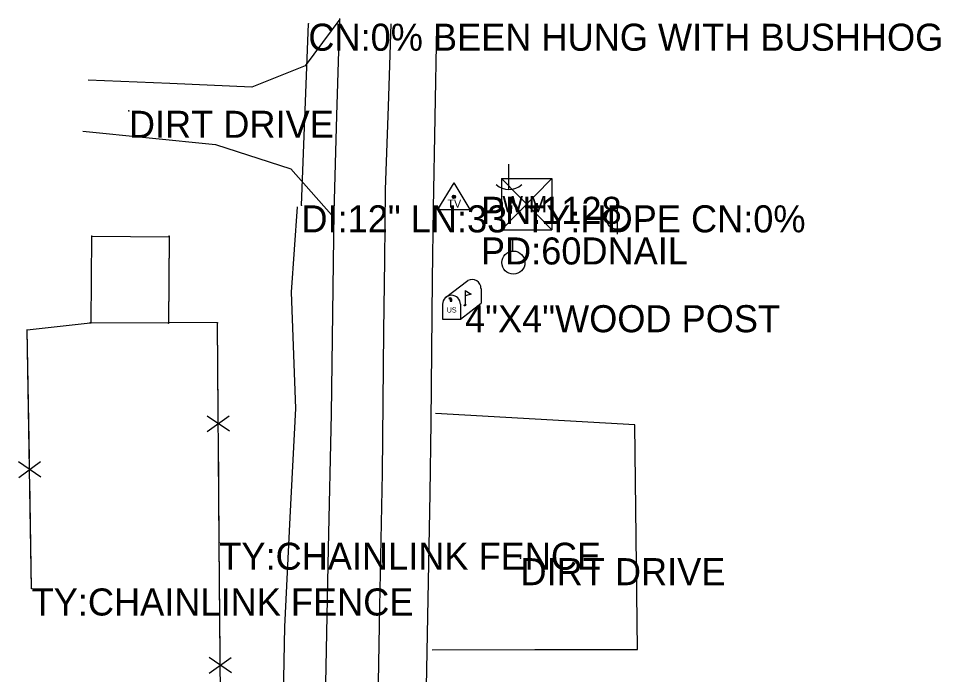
# Model space of a CAD drawing. Extents: x 1050807 to 1053552, y 395828 to 398415.
# Drawn here: x 1051868.7 to 1052039.2, y 398241.2 to 398362.4 of the extents above; entities that cross this region are included whole.
import ezdxf

# ---------------------------------------------------------------- set-up
doc = ezdxf.new("R2010")
doc.units = 0
for name, color, linetype in [('S_BUILDING', 7, 'Continuous'), ('S_CROSS_DRAIN', 7, 'Continuous'), ('S_CROSS_DRAIN_ANNOT', 7, 'Continuous'), ('S_DRG_PT_SYM', 7, 'Continuous'), ('S_DRIVEWAY', 7, 'Continuous'), ('S_EDGE_PAVEMENT', 7, 'Continuous'), ('S_FENCE', 7, 'Continuous'), ('S_FENCE_ANNOT', 7, 'Continuous'), ('S_GRAVEL_ROAD', 7, 'Continuous'), ('S_MAILBOX', 7, 'Continuous'), ('S_MAILBOX_ANNOT', 7, 'Continuous'), ('S_MSC_PT_SYM', 7, 'Continuous'), ('S_PAVEMENT_CROWN', 7, 'Continuous'), ('S_SECONDARY_CTL', 7, 'Continuous'), ('S_SECONDARY_CTL_ANNOT', 7, 'Continuous'), ('S_STR_PT_SYM', 7, 'Continuous'), ('S_SURVEY_TEXT_ANNOT', 7, 'Continuous'), ('S_UTILITY_POLE', 7, 'Continuous'), ('S_WATER_UTILITIES', 7, 'Continuous')]:
    doc.layers.add(name, color=color, linetype=linetype)

msp = doc.modelspace()

# ---------------------------------------------------------------- linework, layer by layer
at = {"layer": 'S_BUILDING'}
for p, q in [((1051882.09, 398306.19), (1051882.22, 398322.19)), ((1051882.22, 398322.19), (1051896.52, 398322.08)), ((1051896.52, 398322.19), (1051896.39, 398306.08)), ((1051896.52, 398322.08), (1051896.39, 398306.08)), ((1051896.39, 398306.08), (1051882.09, 398306.19))]:
    msp.add_line(p, q, dxfattribs=at)
at = {"layer": 'S_CROSS_DRAIN'}
msp.add_line((1051920.99, 398327.88), (1051922.27, 398361.44), dxfattribs=at)
at = {"layer": 'S_DRG_PT_SYM'}
for points in [[(1051922.27, 398361.44), (1051922.27, 398361.49), (1051922.27, 398361.44), (1051922.22, 398361.44), (1051922.27, 398361.44), (1051922.27, 398361.39), (1051922.27, 398361.44), (1051922.32, 398361.44)], [(1051920.99, 398327.88), (1051920.99, 398327.93), (1051920.99, 398327.88), (1051920.94, 398327.88), (1051920.99, 398327.88), (1051920.99, 398327.83), (1051920.99, 398327.88), (1051921.04, 398327.88)]]:
    msp.add_lwpolyline(points, dxfattribs=at)
at = {"layer": 'S_DRIVEWAY'}
for points in [[(1051928.11, 398362.27), (1051921.67, 398353.63), (1051911.81, 398349.74), (1051896.68, 398350.36), (1051881.55, 398350.99)], [(1051880.57, 398341.55), (1051905.13, 398339.1), (1051919.01, 398334.63), (1051926.56, 398326.11)], [(1051945.15, 398245.76), (1051964.14, 398245.8), (1051983.12, 398245.84), (1051982.87, 398266.58), (1051982.61, 398287.32), (1051964.2, 398288.35), (1051945.79, 398289.39)]]:
    msp.add_lwpolyline(points, dxfattribs=at)
at = {"layer": 'S_EDGE_PAVEMENT'}
for points in [[(1051925.48, 398239.54), (1051926, 398264.45), (1051926.52, 398289.36), (1051926.77, 398307.98), (1051927.03, 398326.6), (1051927.55, 398344.5), (1051928.06, 398362.41)], [(1051934.63, 398023.1), (1051930.06, 398027.26), (1051929.8, 398038.82), (1051925.96, 398053.99), (1051931.83, 398077.54), (1051938.69, 398100.99), (1051941.54, 398122.27), (1051942, 398134.91), (1051942.46, 398147.55), (1051942.93, 398160.19), (1051943.39, 398172.83), (1051943.59, 398197.73), (1051943.79, 398222.64), (1051944.04, 398235.63), (1051944.3, 398248.63), (1051944.55, 398261.62), (1051944.81, 398274.62), (1051944.95, 398287.8), (1051945.09, 398300.98), (1051945.24, 398314.17), (1051945.38, 398327.35), (1051945.7, 398344.1), (1051946.02, 398360.85)]]:
    msp.add_lwpolyline(points, dxfattribs=at)
at = {"layer": 'S_FENCE'}
for p, q in [((1051870.31, 398304.86), (1051881.92, 398306.16)), ((1051905.46, 398306.18), (1051896.47, 398306.24)), ((1051905.81, 398265.54), (1051905.46, 398306.18)), ((1051871.11, 398257.09), (1051870.31, 398304.86)), ((1051907.68, 398286.12), (1051903.56, 398288.95)), ((1051907.68, 398286.12), (1051903.56, 398288.95)), ((1051903.58, 398286.08), (1051907.65, 398288.99)), ((1051903.58, 398286.08), (1051907.65, 398288.99)), ((1051872.81, 398277.68), (1051868.67, 398280.48)), ((1051872.81, 398277.68), (1051868.67, 398280.48)), ((1051868.72, 398277.61), (1051872.77, 398280.55)), ((1051868.72, 398277.61), (1051872.77, 398280.55)), ((1051906.18, 398220.91), (1051905.81, 398265.54)), ((1051908.06, 398241.49), (1051903.94, 398244.32)), ((1051908.06, 398241.49), (1051903.94, 398244.32)), ((1051903.96, 398241.46), (1051908.03, 398244.36)), ((1051903.96, 398241.46), (1051908.03, 398244.36))]:
    msp.add_line(p, q, dxfattribs=at)
for points in [[(1051870.31, 398304.86), (1051881.92, 398306.16)], [(1051870.31, 398304.86), (1051881.92, 398306.16)], [(1051905.46, 398306.18), (1051896.47, 398306.24)], [(1051905.46, 398306.18), (1051896.47, 398306.24)], [(1051905.6, 398289.53), (1051905.46, 398306.18)], [(1051905.6, 398289.53), (1051905.46, 398306.18)], [(1051870.71, 398281.08), (1051870.31, 398304.86)], [(1051870.71, 398281.08), (1051870.31, 398304.86)], [(1051905.81, 398265.54), (1051905.63, 398285.53)], [(1051905.81, 398265.54), (1051905.63, 398285.53)], [(1051871.11, 398257.09), (1051870.78, 398277.08)], [(1051871.11, 398257.09), (1051870.78, 398277.08)], [(1051905.98, 398244.91), (1051905.81, 398265.54)], [(1051905.98, 398244.91), (1051905.81, 398265.54)]]:
    msp.add_lwpolyline(points, dxfattribs=at)
at = {"layer": 'S_GRAVEL_ROAD'}
msp.add_lwpolyline([(1051920.21, 398327.61), (1051919.09, 398311.82), (1051919.87, 398290.35), (1051918.86, 398270.17), (1051917.86, 398250), (1051917.52, 398230.91), (1051917.19, 398211.82), (1051915.93, 398189.54), (1051914.68, 398167.26), (1051913.41, 398147.42), (1051912.15, 398127.59), (1051904.68, 398104.16), (1051886.45, 398095.96)], dxfattribs=at)
at = {"layer": 'S_MAILBOX'}
for p, q in [((1051947.63, 398310.86), (1051951.76, 398313.97)), ((1051951.24, 398312.15), (1051951.24, 398309.43)), ((1051954.2, 398312.5), (1051954.2, 398309.78)), ((1051947.08, 398309.59), (1051947.08, 398306.87)), ((1051950.4, 398306.87), (1051954.2, 398309.78)), ((1051950.4, 398309.59), (1051950.4, 398306.87)), ((1051947.08, 398306.87), (1051950.4, 398306.87))]:
    msp.add_line(p, q, dxfattribs=at)
for points in [[(1051951.24, 398312.15), (1051952.35, 398311.49), (1051951.24, 398311.14)], [(1051948.26, 398310.7), (1051948.48, 398310.56), (1051948.48, 398310.18), (1051948.79, 398310.18), (1051948.79, 398310.54), (1051948.59, 398310.79), (1051948.26, 398310.73)]]:
    msp.add_lwpolyline(points, dxfattribs=at)
for centre, end in [((1051952.53, 398312.5), 117.5718), ((1051948.74, 398309.59), 180)]:
    msp.add_arc(centre, 1.66, 0, end, dxfattribs=at)
msp.add_ellipse((1051951.24, 398309.43), major_axis=(0.145, 0.132), ratio=0.564646, dxfattribs=at)
at = {"layer": 'S_MSC_PT_SYM'}
for points in [[(1051889.09, 398345.35), (1051889.09, 398345.4), (1051889.09, 398345.35), (1051889.04, 398345.35), (1051889.09, 398345.35), (1051889.09, 398345.3), (1051889.09, 398345.35), (1051889.14, 398345.35)], [(1051881.92, 398306.16), (1051881.92, 398306.21), (1051881.92, 398306.16), (1051881.87, 398306.16), (1051881.92, 398306.16), (1051881.92, 398306.11), (1051881.92, 398306.16), (1051881.97, 398306.16)], [(1051896.47, 398306.24), (1051896.47, 398306.29), (1051896.47, 398306.24), (1051896.42, 398306.24), (1051896.47, 398306.24), (1051896.47, 398306.19), (1051896.47, 398306.24), (1051896.52, 398306.24)], [(1051905.46, 398306.18), (1051905.46, 398306.23), (1051905.46, 398306.18), (1051905.41, 398306.18), (1051905.46, 398306.18), (1051905.46, 398306.13), (1051905.46, 398306.18), (1051905.51, 398306.18)], [(1051870.31, 398304.86), (1051870.31, 398304.91), (1051870.31, 398304.86), (1051870.26, 398304.86), (1051870.31, 398304.86), (1051870.31, 398304.81), (1051870.31, 398304.86), (1051870.36, 398304.86)], [(1051905.81, 398265.54), (1051905.81, 398265.59), (1051905.81, 398265.54), (1051905.76, 398265.54), (1051905.81, 398265.54), (1051905.81, 398265.49), (1051905.81, 398265.54), (1051905.86, 398265.54)], [(1051961.49, 398262.69), (1051961.49, 398262.74), (1051961.49, 398262.69), (1051961.44, 398262.69), (1051961.49, 398262.69), (1051961.49, 398262.64), (1051961.49, 398262.69), (1051961.54, 398262.69)], [(1051871.11, 398257.09), (1051871.11, 398257.14), (1051871.11, 398257.09), (1051871.06, 398257.09), (1051871.11, 398257.09), (1051871.11, 398257.04), (1051871.11, 398257.09), (1051871.16, 398257.09)]]:
    msp.add_lwpolyline(points, dxfattribs=at)
at = {"layer": 'S_PAVEMENT_CROWN'}
msp.add_lwpolyline([(1051911.73, 398062.49), (1051922.6, 398083.01), (1051926.16, 398095.8), (1051929.71, 398108.59), (1051932.19, 398128.36), (1051932.65, 398140.95), (1051933.12, 398153.54), (1051933.58, 398166.13), (1051934.04, 398178.71), (1051934.3, 398191.33), (1051934.55, 398203.94), (1051934.81, 398216.55), (1051935.06, 398229.16), (1051935.51, 398253.78), (1051935.96, 398278.4), (1051936.1, 398291.5), (1051936.24, 398304.61), (1051936.39, 398317.72), (1051936.53, 398330.82), (1051937.06, 398346.12), (1051937.6, 398361.41)], dxfattribs=at)
at = {"layer": 'S_SECONDARY_CTL'}
for p, q in [((1051949.18, 398332.06), (1051946.17, 398327.11)), ((1051949.18, 398332.06), (1051952.13, 398327.11)), ((1051946.17, 398327.11), (1051952.13, 398327.11))]:
    msp.add_line(p, q, dxfattribs=at)
for radius in [0.311, 0.183, 0.103]:
    msp.add_circle((1051949.18, 398329.45), radius, dxfattribs=at)
at = {"layer": 'S_STR_PT_SYM'}
for points in [[(1051882.22, 398322.19), (1051882.22, 398322.24), (1051882.22, 398322.19), (1051882.17, 398322.19), (1051882.22, 398322.19), (1051882.22, 398322.14), (1051882.22, 398322.19), (1051882.27, 398322.19)], [(1051896.52, 398322.19), (1051896.52, 398322.24), (1051896.52, 398322.19), (1051896.47, 398322.19), (1051896.52, 398322.19), (1051896.52, 398322.14), (1051896.52, 398322.19), (1051896.57, 398322.19)], [(1051896.52, 398322.08), (1051896.52, 398322.13), (1051896.52, 398322.08), (1051896.47, 398322.08), (1051896.52, 398322.08), (1051896.52, 398322.03), (1051896.52, 398322.08), (1051896.57, 398322.08)], [(1051882.09, 398306.19), (1051882.09, 398306.24), (1051882.09, 398306.19), (1051882.04, 398306.19), (1051882.09, 398306.19), (1051882.09, 398306.14), (1051882.09, 398306.19), (1051882.14, 398306.19)], [(1051896.39, 398306.08), (1051896.39, 398306.13), (1051896.39, 398306.08), (1051896.34, 398306.08), (1051896.39, 398306.08), (1051896.39, 398306.03), (1051896.39, 398306.08), (1051896.44, 398306.08)], [(1051896.39, 398306.08), (1051896.39, 398306.13), (1051896.39, 398306.08), (1051896.34, 398306.08), (1051896.39, 398306.08), (1051896.39, 398306.03), (1051896.39, 398306.08), (1051896.44, 398306.08)]]:
    msp.add_lwpolyline(points, dxfattribs=at)
at = {"layer": 'S_UTILITY_POLE'}
for p, q in [((1051959.29, 398335.5), (1051959.29, 398330.78)), ((1051979.41, 398322.57), (1051979.41, 398328.36)), ((1051960.06, 398319.44), (1051960.06, 398321.55))]:
    msp.add_line(p, q, dxfattribs=at)
for centre, radius in [((1051979.41, 398325.5), 2.05), ((1051960.18, 398317.3), 2.13)]:
    msp.add_circle(centre, radius, dxfattribs=at)
msp.add_arc((1051959.36, 398334.2), 3.41, 226.3972, 313.6028, dxfattribs=at)
at = {"layer": 'S_WATER_UTILITIES'}
for p, q in [((1051957.96, 398332.83), (1051967.3, 398332.83)), ((1051957.96, 398332.83), (1051957.96, 398323.33)), ((1051957.96, 398332.83), (1051967.3, 398323.33)), ((1051967.3, 398332.83), (1051957.96, 398323.33)), ((1051967.3, 398332.83), (1051967.3, 398323.33)), ((1051957.96, 398323.33), (1051967.3, 398323.33))]:
    msp.add_line(p, q, dxfattribs=at)

# ---------------------------------------------------------------- texts
at = {"layer": 'S_CROSS_DRAIN_ANNOT'}
for s, p in [('CN:0% BEEN HUNG WITH BUSHHOG', (1051922.27, 398356.44)), ('DI:12" LN:33\' TY:HDPE CN:0%', (1051920.99, 398322.88))]:
    msp.add_text(s, height=5, dxfattribs=at).set_placement(p)
at = {"layer": 'S_FENCE_ANNOT'}
for p in [(1051905.81, 398260.54), (1051871.11, 398252.09)]:
    msp.add_text('TY:CHAINLINK FENCE', height=5, dxfattribs=at).set_placement(p)
at = {"layer": 'S_MAILBOX'}
msp.add_text('US', height=0.96, dxfattribs=at).set_placement((1051947.84, 398308.07))
at = {"layer": 'S_MAILBOX_ANNOT'}
msp.add_text('4"X4"WOOD POST', height=5, dxfattribs=at).set_placement((1051951.24, 398304.43))
at = {"layer": 'S_SECONDARY_CTL'}
msp.add_text('TV', height=1.5, dxfattribs=at).set_placement((1051947.97, 398327.44))
at = {"layer": 'S_SECONDARY_CTL_ANNOT'}
for s, p in [('PN:1128', (1051954.18, 398324.45)), ('PD:60DNAIL', (1051954.18, 398316.95))]:
    msp.add_text(s, height=5, dxfattribs=at).set_placement(p)
at = {"layer": 'S_SURVEY_TEXT_ANNOT'}
for p in [(1051889.09, 398340.35), (1051961.49, 398257.69)]:
    msp.add_text('DIRT DRIVE', height=5, dxfattribs=at).set_placement(p)
at = {"layer": 'S_WATER_UTILITIES'}
msp.add_text('W M', height=3, dxfattribs=at).set_placement((1051958.16, 398326.59))

doc.saveas('drawing.dxf')
